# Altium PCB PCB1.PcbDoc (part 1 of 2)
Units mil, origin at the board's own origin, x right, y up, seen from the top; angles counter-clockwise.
Board outline 4950 x 3450 mil, 4 copper layers (Top Layer, VCC, GND, Bottom Layer), stack 79.834 mil thick; 154 components, 59 nets, 358 pads, 74 vias.
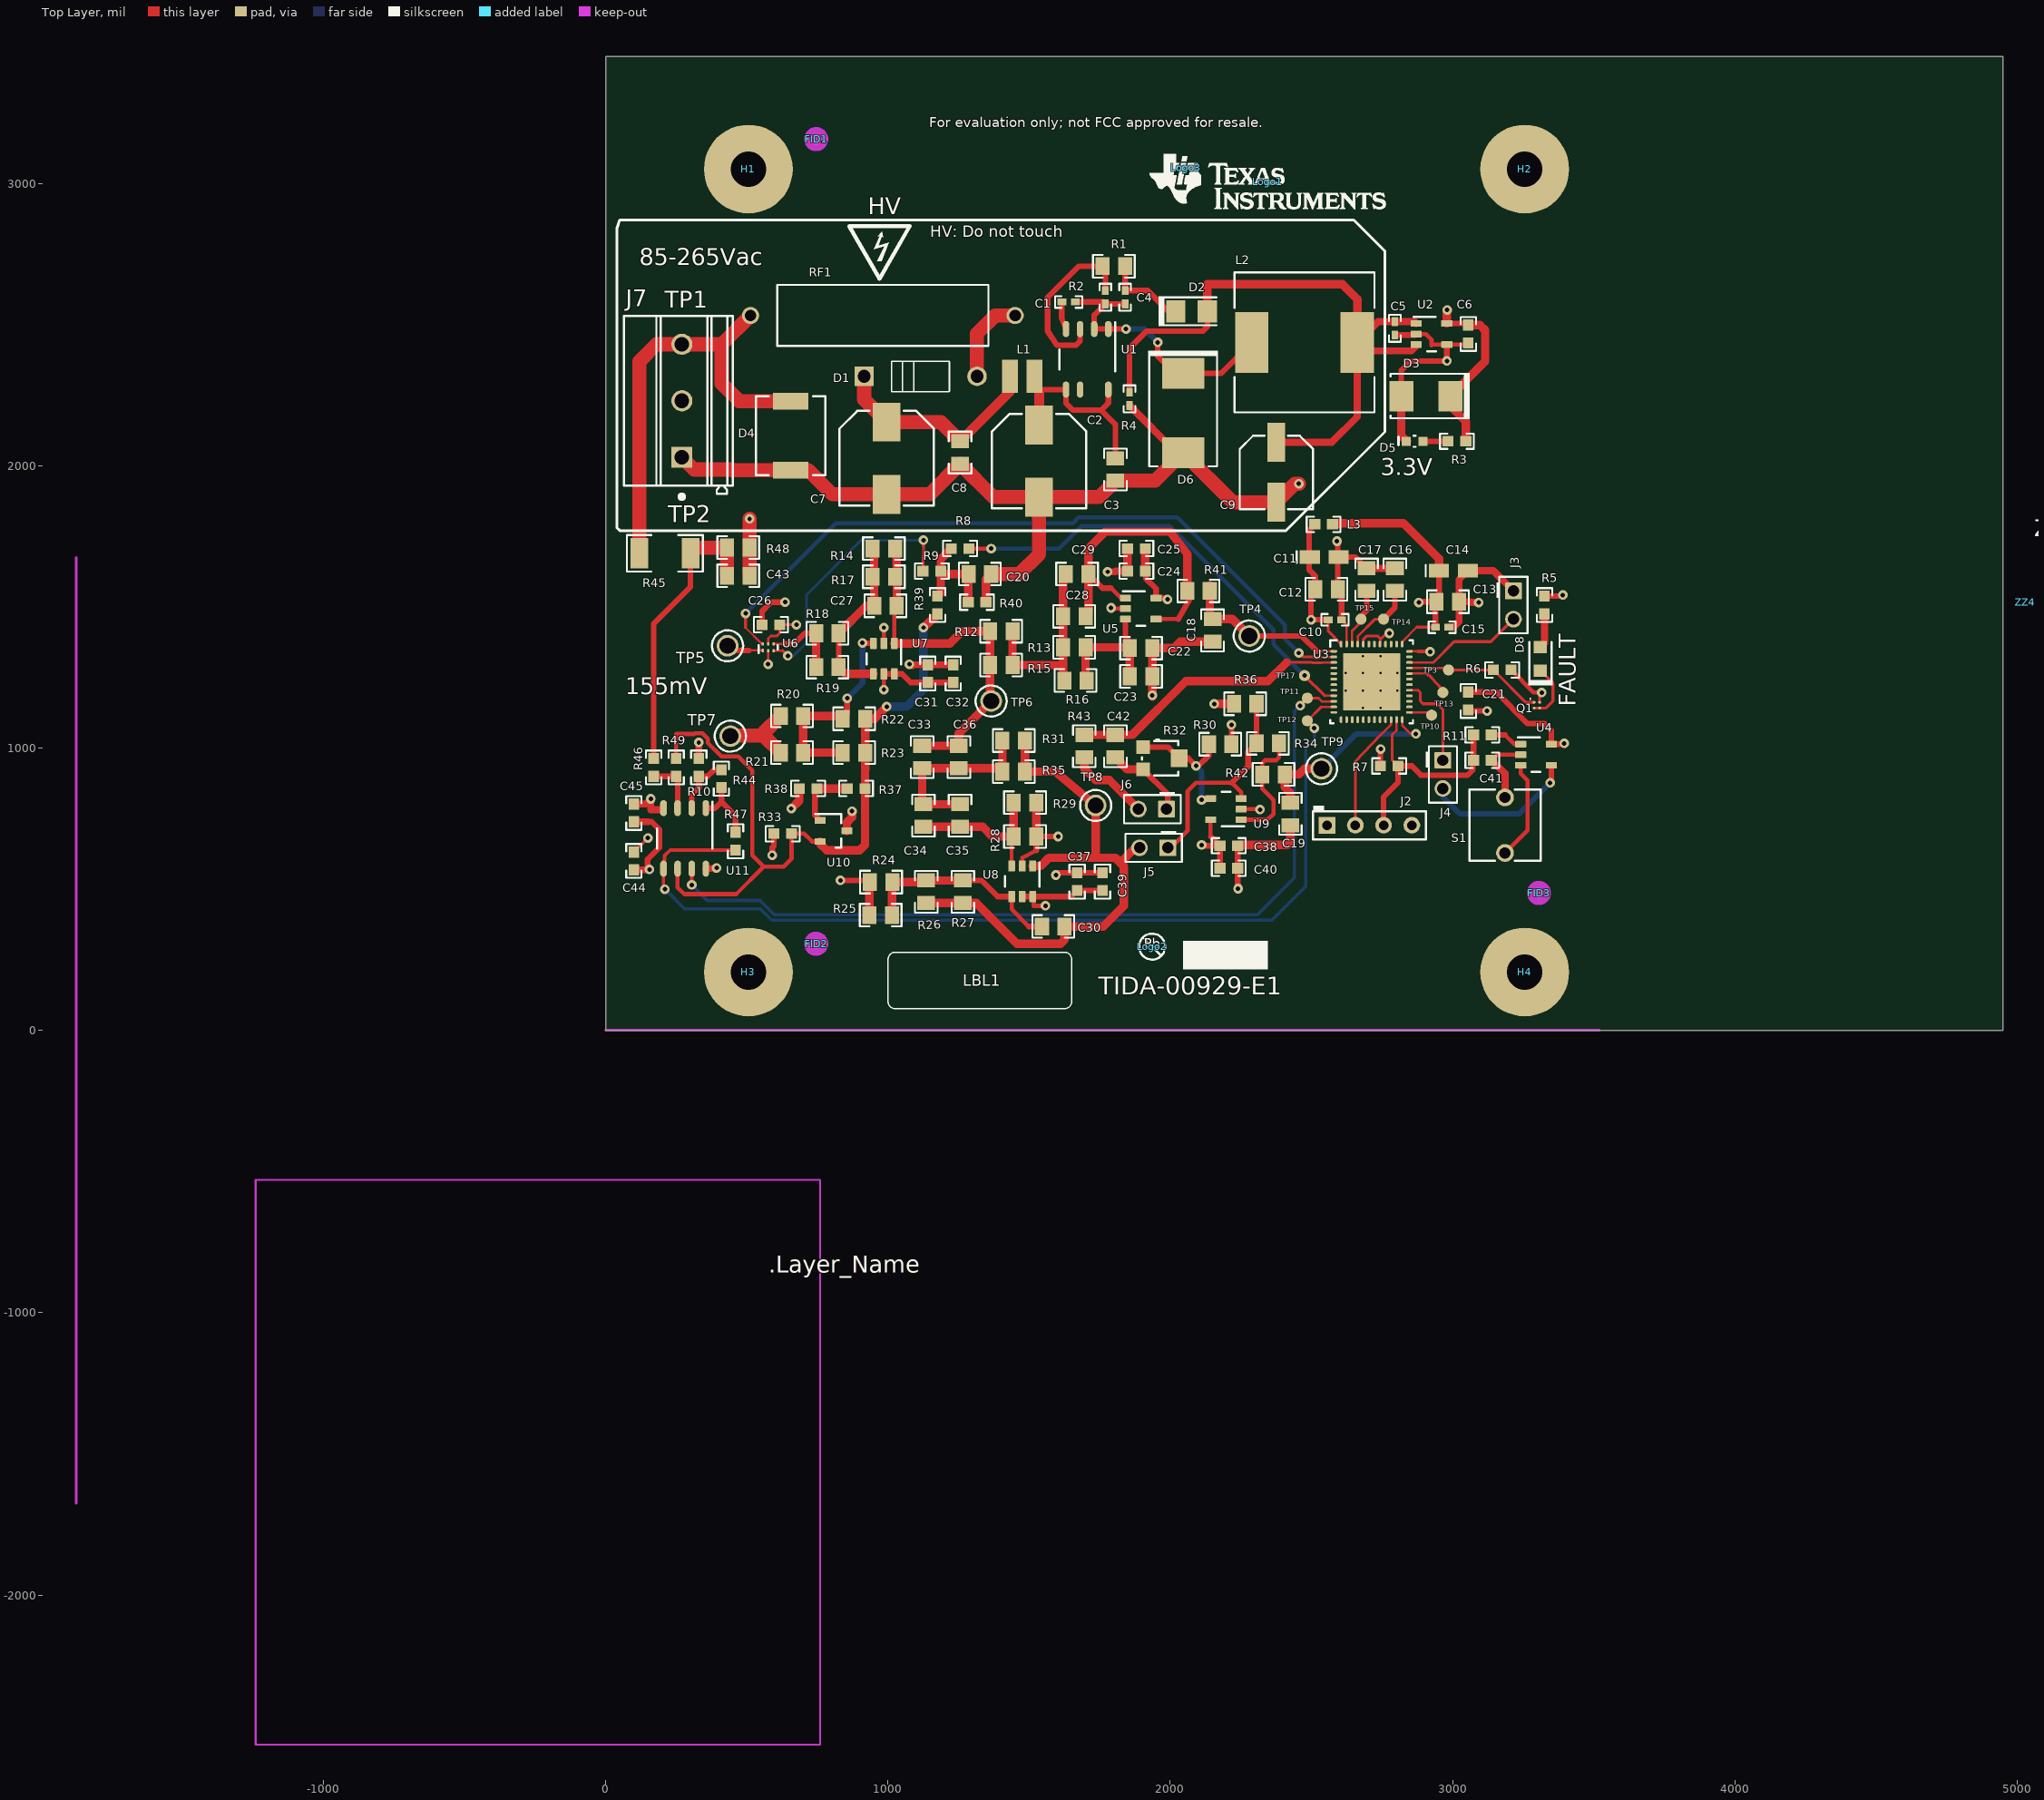
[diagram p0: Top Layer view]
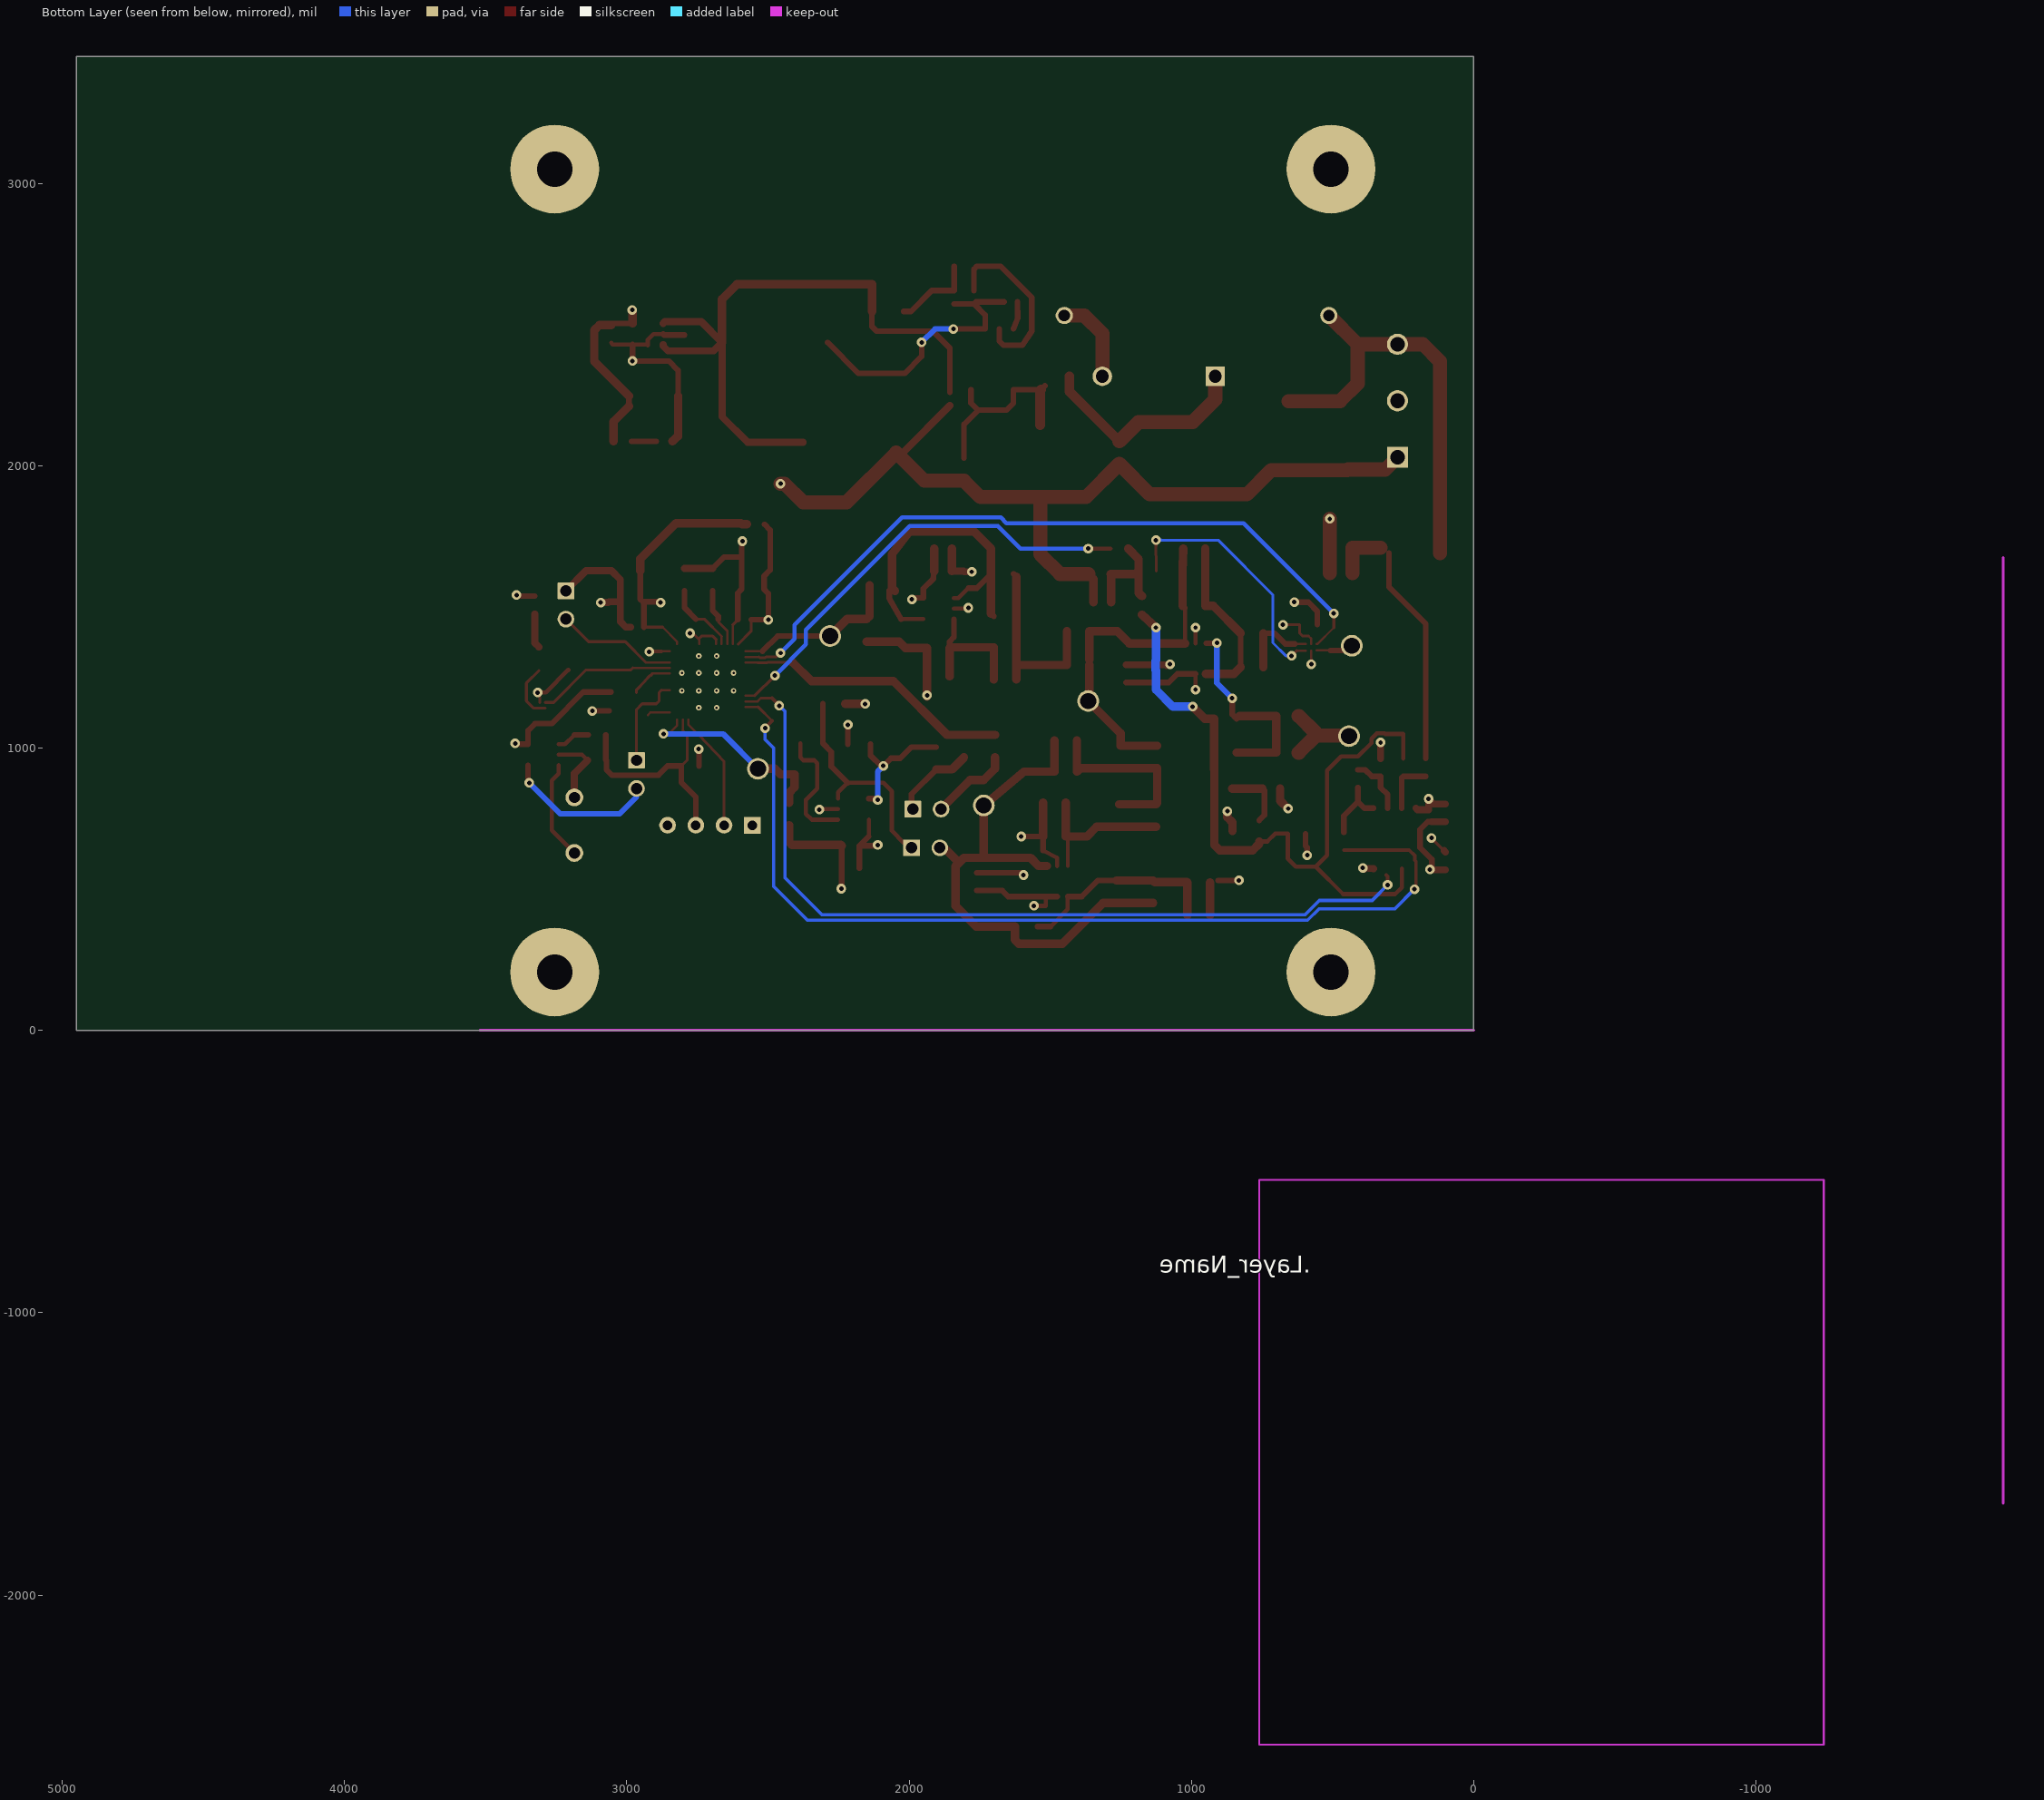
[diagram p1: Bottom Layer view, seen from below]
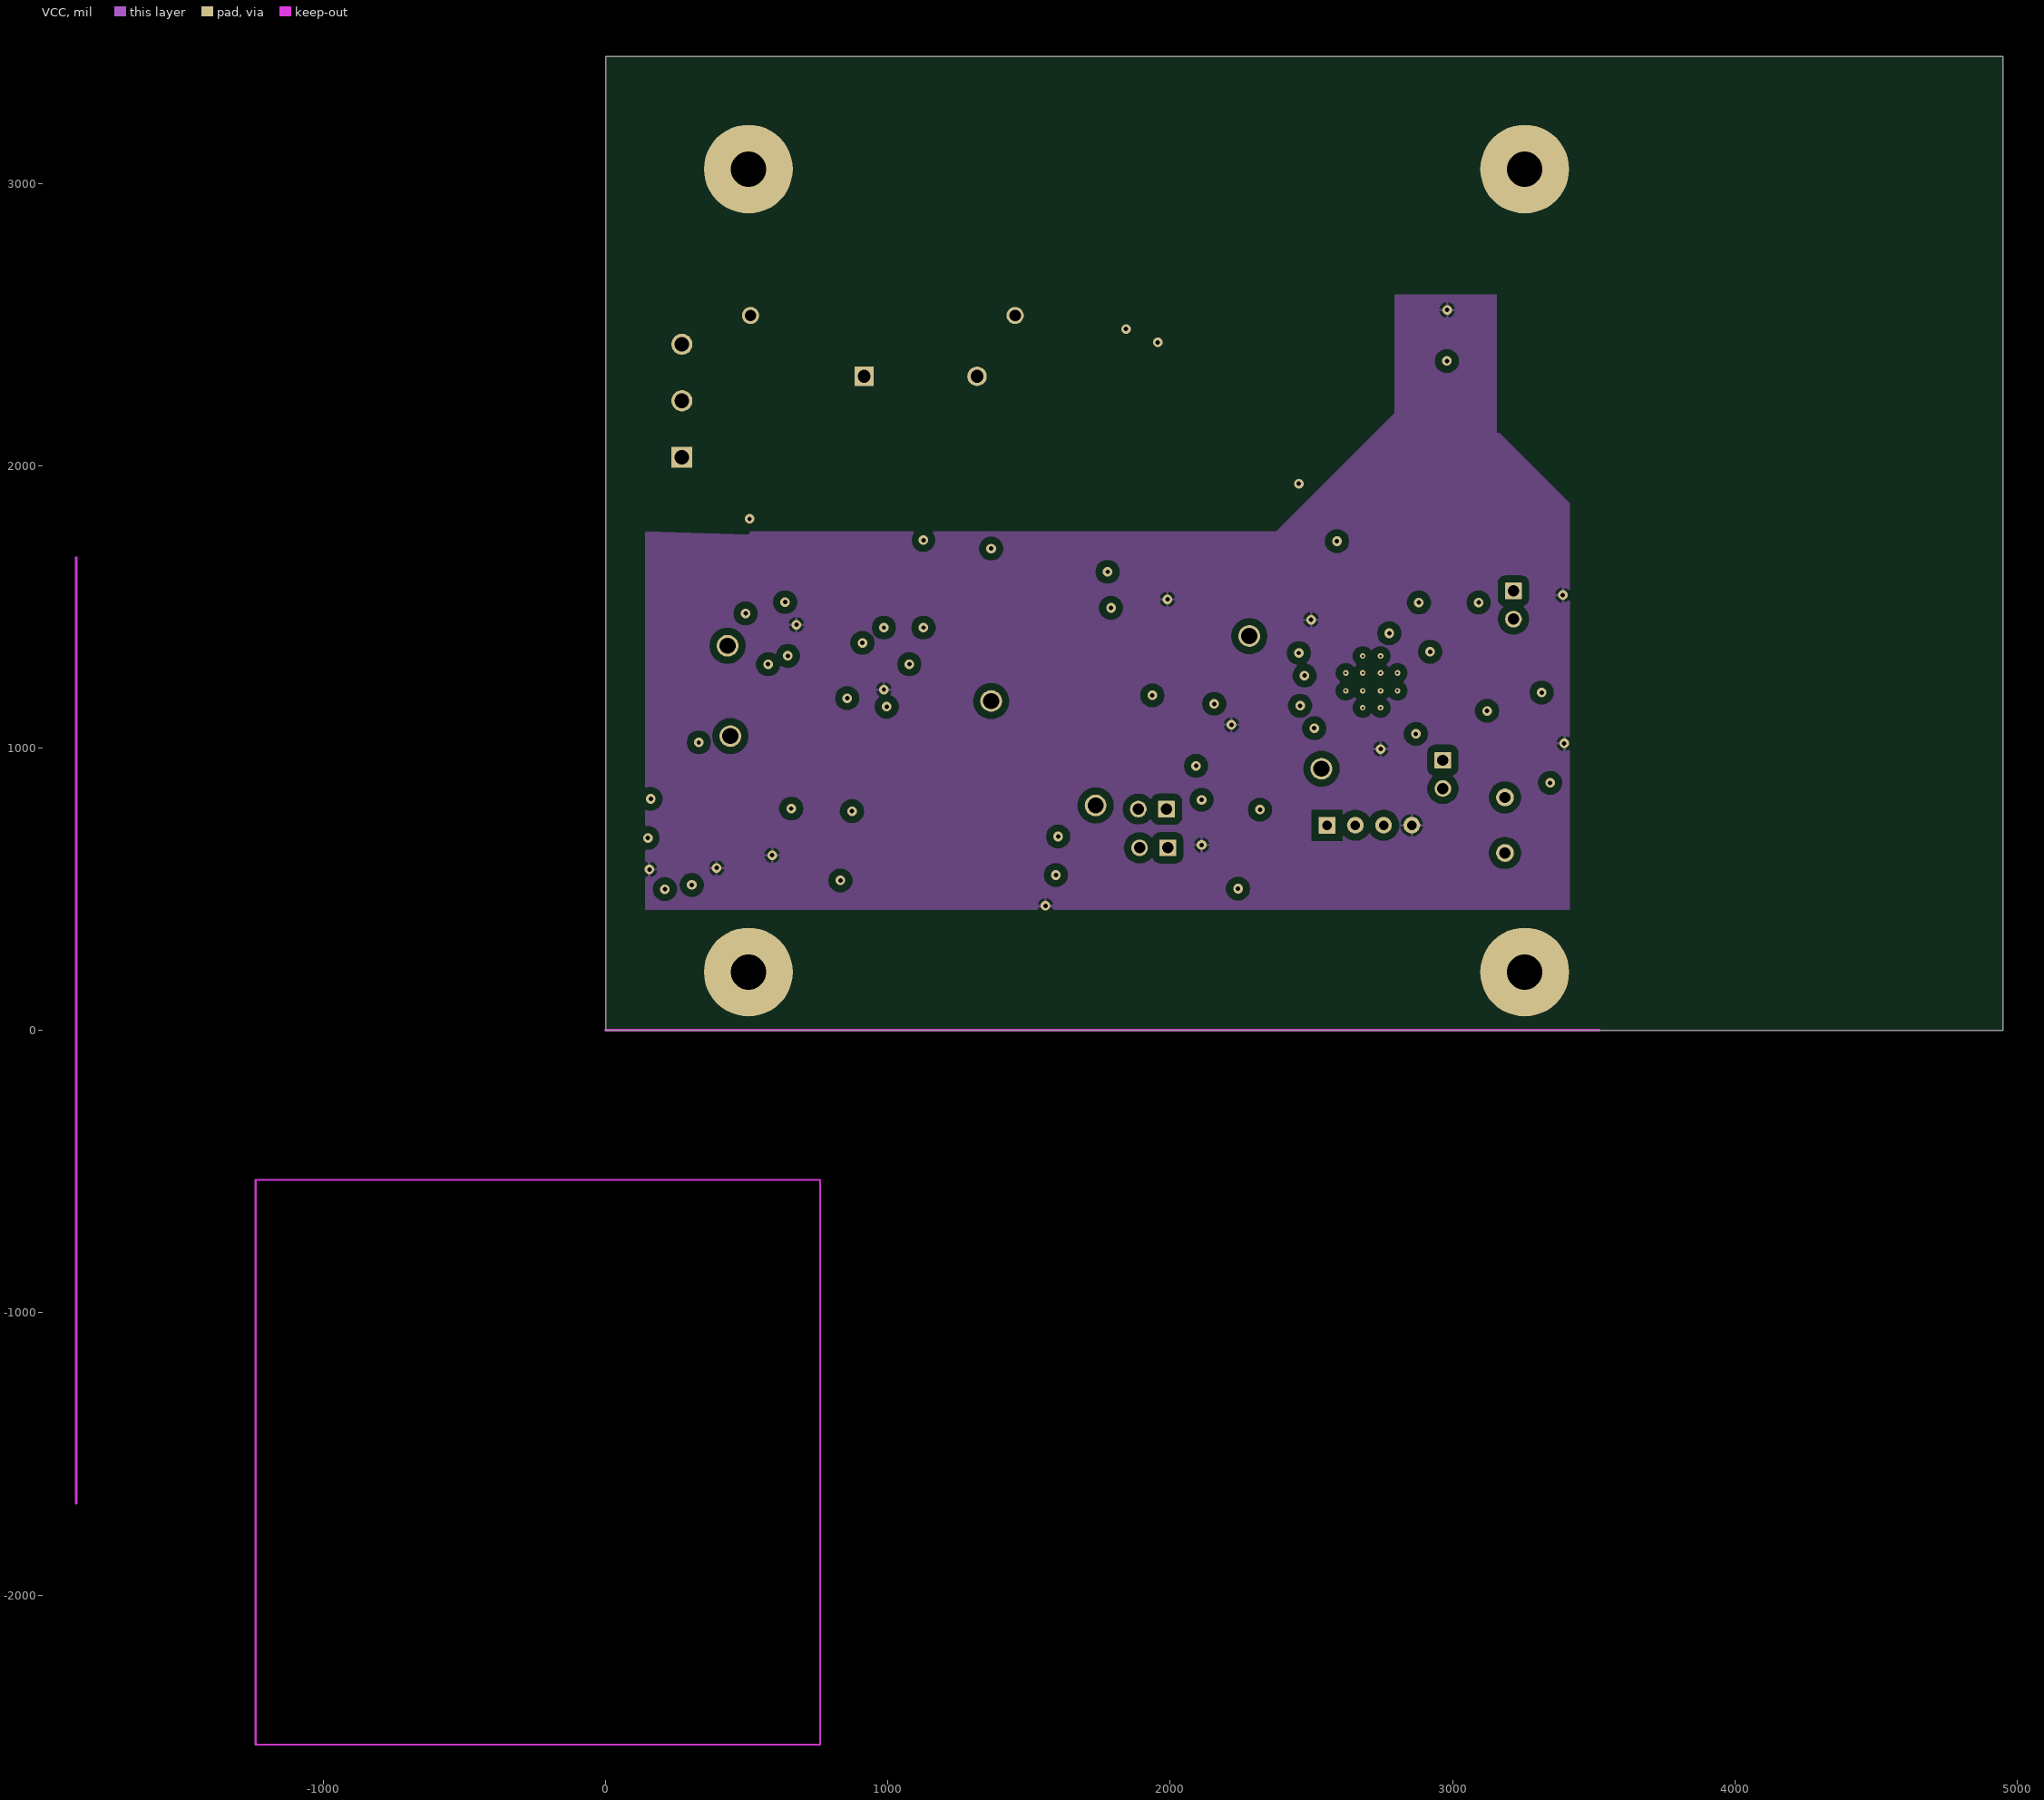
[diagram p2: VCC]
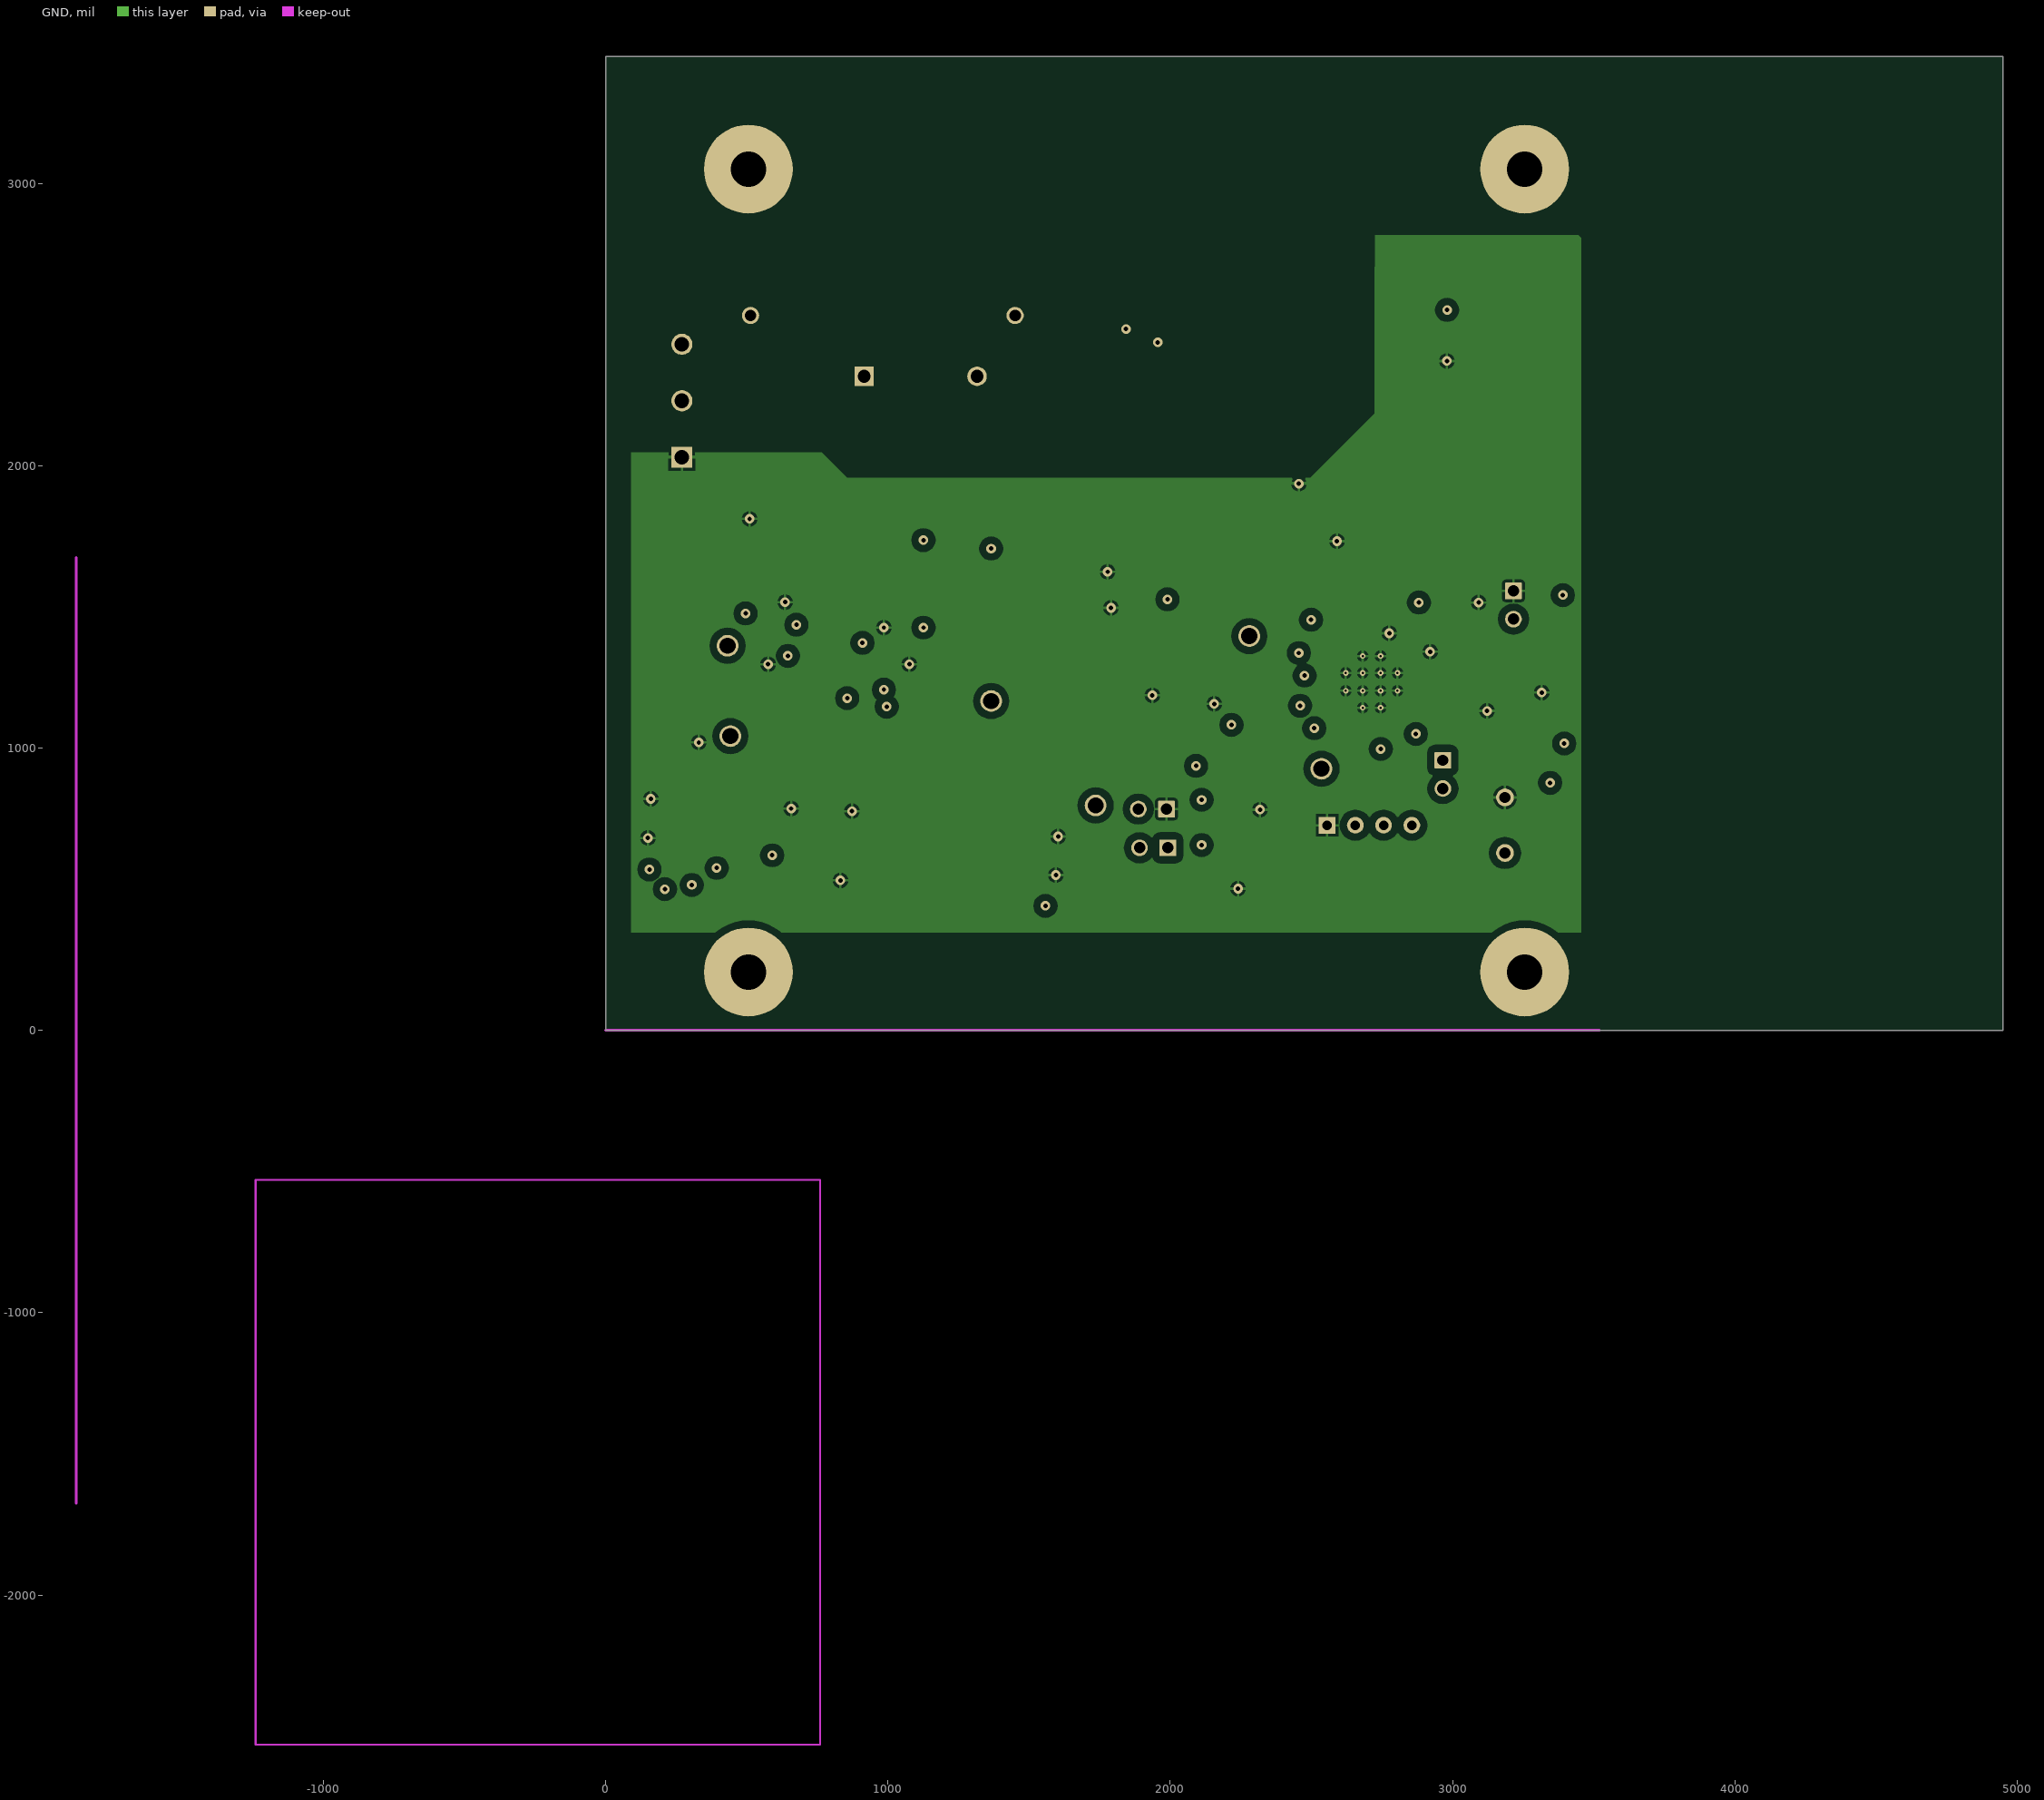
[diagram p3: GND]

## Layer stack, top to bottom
Top Solder: solder mask 0.4, Solder Resist, Dk 3.5
Top Layer: signal copper 1.4
Dielectric1: core 59.2, FR-4, Dk 4.8
VCC: signal copper 1.417
Dielectric 3: prepreg 5, Dk 4.2
GND: signal copper 1.417
Dielectric 2: core 10, Dk 4.2
Bottom Layer: signal copper 1.4
Bottom Solder: solder mask 0.4, Solder Resist, Dk 3.5

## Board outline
0,0 4950,0 4950,3450 0,3450

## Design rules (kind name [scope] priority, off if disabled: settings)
AcuteAngle [All] p1: minimum=4.50000000000000E+0001 checktracksonly=FALSE
AssemblyTestPointUsage [All] p1: valid=2
BoardOutlineClearance BoardOutlineClearance_MountingHoles [OnCopper and InComponentClass('Mounting Holes')] p1: gap=40
BoardOutlineClearance BoardOutlineClearance_Poly [OnCopper and IsPoly] p2: gap=25
BoardOutlineClearance [OnCopper and Not InComponentClass('Logo') and not InComponentClass('FiducialMark') and not InRegion(1000,500,4000,800) and not InPoly] p3: gap=75
Clearance Clearance_Keepouts [((IsTrack Or IsArc) And Not InPoly) And IsFree and IsKeepOut vs ((IsTrack Or IsArc) And Not InPoly) And IsFree and IsKeepOut] p1: gap=0
Clearance Clearance_Poly [InPolygon] p2: gap=25
Clearance [All] p3: gap=7.87
ComponentClearance ComponentClearance_MountingHoles_FiducialMarks [InComponentClass('Mounting Holes') vs InComponentClass('FiducialMark')] p1: gap=50 collisioncheckmode=3 verticalgap=10 showdistances=FALSE
ComponentClearance ComponentClearance_Shunt [InComponentClass('Header') vs InComponentClass('Shunt')] p2: gap=0 collisioncheckmode=3 verticalgap=0 showdistances=FALSE
ComponentClearance ComponentClearance_Logo [InComponentClass('Logo')] p3: gap=50 collisioncheckmode=3 verticalgap=10 showdistances=FALSE
ComponentClearance ComponentClearance_ScrewToNut [(HasFootprint('NY PMS 440 0025 PH')) vs (HasFootprint('Keystone_1902C'))] p4: gap=5 collisioncheckmode=3 verticalgap=10 showdistances=FALSE
ComponentClearance ComponentClearance_MountingHoles [InComponentClass('Mounting Holes')] p5: gap=250 collisioncheckmode=3 verticalgap=100000 showdistances=FALSE
ComponentClearance ComponentClearance_SmallPassives [HasFootprint('0201*') or HasFootprint('0402*') or HasFootprint('0508') or HasFootprint('0603*') or HasFootprint('0612') or HasFootprint('0805*') or HasFootprint('0815*') or HasFootprint('0830*') or HasFootprint('1206*') or HasFootprint('1210*') or HasFootprint('1808*') or HasFootprint('1812*') or HasFootprint('1825*') or HasFootprint('2010*') or HasFootprint('2220*') or HasFootprint('2225*') or HasFootprint('2512*') or HasFootprint('2728*') or HasFootprint('3518*') vs HasFootprint('0201*') or HasFootprint('0402*') or HasFootprint('0508') or HasFootprint('0603*') or HasFootprint('0612') or HasFootprint('0805*') or HasFootprint('0815*') or HasFootprint('0830*') or HasFootprint('1206*') or HasFootprint('1210*') or HasFootprint('1808*') or HasFootprint('1812*') or HasFootprint('1825*') or HasFootprint('2010*') or HasFootprint('2220*') or HasFootprint('2225*') or HasFootprint('2512*') or HasFootprint('2728*') or HasFootprint('3518*')] p6: gap=14.96 collisioncheckmode=3 verticalgap=10 showdistances=FALSE
ComponentClearance ComponentClearance_THtoSMT [IsThruComponent vs IsSMTComponent] p7: gap=40 collisioncheckmode=3 verticalgap=30 showdistances=FALSE
ComponentClearance ComponentClearance_THtoTH [IsThruComponent vs IsThruComponent] p8: gap=30 collisioncheckmode=3 verticalgap=30 showdistances=FALSE
ComponentClearance [All] p9: gap=30 collisioncheckmode=3 verticalgap=10 showdistances=FALSE
DiffPairsRouting [All] p1: maxlimit=100 minlimit=10 mostfreqgap=10 toplayer_minwidth=15 toplayer_maxwidth=15 toplayer_prefwidth=15 midlayer1_minwidth=15 midlayer1_maxwidth=15 midlayer1_prefwidth=15 midlayer2_minwidth=15 midlayer2_maxwidth=15 midlayer2_prefwidth=15 bottomlayer_minwidth=15 bottomlayer_maxwidth=15 bottomlayer_prefwidth=15 maxuncoupledlength=1000
FabricationTestPointUsage TestPointUsage [All] p1: valid=2 allowmultiple=FALSE
FabricationTestpoint Testpoint [All] p1: side=3 testpointundercomponent=TRUE minsize=40 maxsize=100 preferedsize=60 minholesize=0 maxholesize=40 preferedholesize=32 testpointgrid=1 allowsidetop=TRUE allowsidebottom=TRUE usegrid=TRUE gridtolerance=0.01
FanoutControl Fanout_LCC [IsLCC] p1: bgadir=Out bgaviamode=Centered fanoutstyle=Auto fanoutdirection=Alternating viagrid=1 // Fanout_LCC (Default Rule)
FanoutControl Fanout_BGA [IsBGA] p2: bgadir=Out bgaviamode=Centered fanoutstyle=Auto fanoutdirection=Alternating viagrid=1 // Fanout_BGA (Default Rule)
FanoutControl Fanout_Default [All] p4: bgadir=Out bgaviamode=Centered fanoutstyle=Auto fanoutdirection=Alternating viagrid=1 // Fanout_Default (Default Rule)
FanoutControl Fanout_Small [(CompPinCount < 5)] p5: bgadir=Out bgaviamode=Centered fanoutstyle=Auto fanoutdirection=OutThenIn viagrid=1 // Fanout_Small (Default Rule)
HoleSize [All] p1: absolutevalues=TRUE maxlimit=251 minlimit=7.87 maxpercent=80.000 minpercent=20.000
MinimumAnnularRing MinimumAnnularRing_ThermalPadVias [IsVia and InAnyComponent] p1: minimumring=5.91
MinimumAnnularRing [All] p2: minimumring=8
MinimumSolderMaskSliver MinimumSolderMaskSliver_Logo [InComponentClass('Logo') vs InComponentClass('Logo')] p1: minsoldermaskwidth=0.7
MinimumSolderMaskSliver [All] p2: minsoldermaskwidth=3.94
PlaneConnect [All] p1: planeconnectstyle=Relief reliefexpansion=10 reliefentries=4 reliefconductorwidth=10 reliefairgap=10
PolygonConnect [All] p1: connectstyle=Relief reliefconductorwidth=10 reliefentries=4 polygonreliefangle="90 Angle" airgapwidth=10
RoutingVias ThermalPadVias [IsVia and InAnyComponent] p1: holewidth=7.87 width=19.68 viastyle="Through Hole" minholewidth=7.87 minwidth=19.68 maxholewidth=12.99 maxwidth=23.62
RoutingVias [All] p2: holewidth=16 width=34 viastyle="Through Hole" minholewidth=7.87 minwidth=26 maxholewidth=40 maxwidth=65
SilkToBoardRegionClearance [Not ((IsComment or IsDesignator) And (Hide <> 'False')) and not InRegion(1000,500,4000,800)] p1:
SilkToSilkClearance SilkToSilkClearance_Pb-FreeLogo [(HasFootprint('Pb-Free_Overlay_Medium') OR HasFootprint('Pb-Free_Overlay_Small')) vs (HasFootprint('Pb-Free_Overlay_Medium') OR HasFootprint('Pb-Free_Overlay_Small'))] p1: silktosilkclearance=0
SilkToSilkClearance [All] p2: silktosilkclearance=4
SilkToSolderMaskClearance SilkToComponentPadClearance [IsPad and InAnycomponent] p1: minsilkscreentomaskgap=5 clearancetoexposedcopper=TRUE
SilkToSolderMaskClearance "Silk to Solder Mask Opening" [All] p2: minsilkscreentomaskgap=4 clearancetoexposedcopper=FALSE
SolderMaskExpansion [All] p1: expansion=1.97
Width [All] p1: maxlimit=100 minlimit=6 preferedwidth=10 checkconnectedcopper=TRUE
15 further rules are at their usual default settings.

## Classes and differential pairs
component class Label: LBL1
component class AssemblyNote: ZZ1 ZZ2 ZZ3 ZZ4
component class FiducialMark: FID1 FID2 FID3
component class EVM_Hardware: FID1 FID2 FID3 H1 H2 H3 H4 HV LBL1 Logo1 Logo2 Logo3 ZZ1 ZZ2 ZZ3 ZZ4
component class Logo: Logo1
component class "Mounting Holes": H1 H2 H3 H4
component class Header: J2 J3 J4 J5 J6
component class Sheet1: C1 C2 C3 C4 C5 C6 C7 C8 C9 C10 C11 C12 C13 C14 C15 C16 C17 C20 C21 C41 D1 D2 D3 D4 D5 D6 D8 J1 J2 J3 J4 J7 L1 L2 L3 Q1 R1 R2 R3 R4 R5 R6 R7 R8 R9 R11 R39 R40 RF1 S1 TP3 TP10 TP11 TP12 TP13 TP14 TP15 TP17 U1 U2 U3 U4
component class Sheet2: C18 C19 C22 C23 C24 C25 C26 C27 C28 C29 C30 C31 C32 C33 C34 C35 C36 C37 C38 C39 C40 C42 C43 C44 C45 J5 J6 R10 R12 R13 R14 R15 R16 R17 R18 R19 R20 R21 R22 R23 R24 R25 R26 R27 R28 R29 R30 R31 R32 R33 R34 R35 R36 R37 R38 R41 R42 R43 R44 R45 R46 R47 R48 R49 TP4 TP5 TP6 TP7 TP8 TP9 U5 U6 U7 U8 U9 U10 U11

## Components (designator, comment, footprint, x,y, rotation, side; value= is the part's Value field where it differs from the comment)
C1 "C1005X5R1A104K050BA" 0402 1640.04,2580.03 r0 top
C2 "ULR2H2R7MNL1GS" ULR_800X1000 1535.59,2016.56 r270 top
C3 "CC0805JRNP09BN101" 0805_HV 1805.59,1986.56 r270 top
C4 "GRM155R61A683KA01D" 0402 1840.04,2596.56 r270 top
C5 "GRM155R61A105KE15D" 0402 2795.59,2486.56 r270 top
C6 "GRM188R61A335KE15D" 0603 3055.59,2466.56 r270 top
C7 "ULR2H2R7MNL1GS" ULR_800X1000 995.59,2026.56 r270 top
C8 "CC0805JRNP09BN101" 0805_HV 1255.59,2046.56 r270 top
C9 "UUD1A680MCL1GS" SM_RADIAL_6.3AMM 2375.59,1976.56 r270 top
C10 "C1005X5R1A104K050BA" 0402 2583.29,1454.26 r0 top
C11 "TAJA106M010RNJ" 3216-18 2545.59,1676.56 r0 top
C12 "LMK212B7105KD-T" 0805_HV 2553.29,1562.36 r0 top
C13 "LMK212B7105KD-T" 0805_HV 2983.29,1518.02 r0 top
C14 "TAJA106M010RNJ" 3216-18 3003.29,1628.02 r0 top
C15 "C1005X5R1A104K050BA" 0402 2963.29,1428.02 r0 top
C16 "GQM2195C1H220JB01D" 0805_HV 2795.59,1596.56 r270 top
C17 "GQM2195C1H220JB01D" 0805_HV 2695.59,1596.56 r270 top
C18 "GQM2195C2A100JB01D" 0805_HV 2150,1416.56 r270 top
C19 "GQM2195C2A100JB01D" 0805_HV 2425.59,766.56 r270 top
C20 "GQM2195C1H220JB01D" 0805_HV 1325.59,1616.56 r0 top
C21 "06033C104JAT2A" 0603 3055.59,1166.56 r270 top
C22 "CC0805JRNP09BN101" 0805_HV 1896.69,1353.94 r180 top
C23 "CC0805JRNP09BN101" 0805_HV 1896.69,1253.94 r180 top
C24 "C1608X7R1C105K080AC" 0603 1880,1626.56 r180 top
C25 "06033C104JAT2A" 0603 1880,1706.56 r180 top
C26 "06033C104JAT2A" 0603 585.59,1436.56 r0 top
C27 "GQM2195C1H220JB01D" 0805_HV 991.2,1503.63 r0 top
C28 "GRM2165C1H221JA01D" 0805_HV 1660,1466.56 r180 top
C29 "GRM2165C1H221JA01D" 0805_HV 1670,1616.56 r180 top
C30 "GQM2195C1H220JB01D" 0805_HV 1585.59,368.02 r0 top
C31 "C1608X7R1C105K080AC" 0603 1141.2,1263.63 r90 top
C32 "06033C104JAT2A" 0603 1231.2,1263.63 r90 top
C33 "GRM216R71E102KA01D" 0805_HV 1121.2,968.02 r90 top
C34 "GRM216R71E102KA01D" 0805_HV 1125.59,760.95 r90 top
C35 "GRM216R71E102KA01D" 0805_HV 1255.59,760.95 r90 top
C36 "GRM216R71E102KA01D" 0805_HV 1251.2,968.02 r90 top
C37 "C1608X7R1C105K080AC" 0603 1670,526.56 r90 top
C38 "C1608X7R1C105K080AC" 0603 2207.42,653.94 r0 top
C39 "06033C104JAT2A" 0603 1760,526.56 r90 top
C40 "06033C104JAT2A" 0603 2207.42,573.94 r0 top
C41 "06035C132JAT2A" 0603 3105.59,956.56 r0 top
C42 "GQM2195C2A100JB01D" 0805_HV 1805.59,1006.56 r270 top
C43 "GRM216R71E102KA01D" 0805_HV 470,1610 r0 top
C44 "C1608X7R1C105K080AC" 0603 100,600 r90 top
C45 "06033C104JAT2A" 0603 100,770 r90 top
D1 "1N4007" DO-41 1115.59,2316.56 r0 top
D2 "CD1408-FU1800" Diode_1408 2075.59,2546.56 r0 top
D3 "1SMB5914BT3G" SMB 2905.28,2246.56 r180 top
D4 "SMCJ400CA" DO-214AB-Bi 655.59,2106.56 r90 top
D5 "LG L29K-G2J1-24-Z" "LG L29K_GREEN" 2865.28,2086.56 r180 top
D6 "ES3J" SMC 2045.59,2186.56 r270 top
D8 "150080SS75000" WL-SMCW_RED_0805 3310.99,1315.92 r90 top
FID1 "Fiducial" Fiducial10-20 745.59,3156.56 r0 top
FID2 "Fiducial" Fiducial10-20 745.59,306.56 r0 top
FID3 "Fiducial" Fiducial10-20 3305.59,486.56 r0 top
H1 "NY PMS 440 0025 PH" "NY PMS 440 0025 PH" 505.59,3050.56 r0 top locked
H2 "NY PMS 440 0025 PH" "NY PMS 440 0025 PH" 3255.59,3050.56 r0 top locked
H3 "NY PMS 440 0025 PH" "NY PMS 440 0025 PH" 505.59,206.56 r0 top locked
H4 "NY PMS 440 0025 PH" "NY PMS 440 0025 PH" 3255.59,206.56 r0 top locked
HV "DANGER HIGH VOLTAGE" IEC_HighVoltage_Small 970,2760 r180 top
J2 "800-10-004-10-001000" Mill-Max_800-10-004-10-001000 2705.59,726.56 r0 top
J3 "PEC02SAAN" CONN_PEC02SAAN 3215.59,1506.56 r270 top
J4 "PEC02SAAN" CONN_PEC02SAAN 2965.59,906.56 r270 top
J5 "PEC02SAAN" CONN_PEC02SAAN 1941.18,646.56 r180 top
J6 "PEC02SAAN" CONN_PEC02SAAN 1936.79,783.63 r180 top
J7 "1715734" Phoenix_1715734 270,2230 r90 top
L1 "SDR0302-471KL" SDR0302 1475.59,2316.56 r0 top
L2 "MSS1210-125KE" MSS1210 2475.59,2436.56 r0 top
L3 "BLM18SG331TN1D" 0603 2543.29,1792.36 r180 top
LBL1 "Size: 0.65\" x 0.20 \"" Label_650x200 1325.59,176.56 r0 top
Logo1 "Texas Instruments" TI_Stacked_Overlay_Small 2345.59,3006.56 r0 top
Logo2 "Pb-Free Symbol" Pb-Free_Overlay_Small 1935.59,296.56 r0 top
Logo3 "FCC disclaimer" FCC_disclaimer 2055.59,3056.56 r0 top
Q1 "CSD13201W10" uSMD_4A 3298.69,1151.72 r0 top
R1 "RT0805BRD0739K7L" 0805_HV 1800.04,2706.56 r0 top
R2 "CRCW040210K2FKED" 0402 1770.04,2596.56 r90 top
R3 "CRCW0603300RJNEA" 0603 3015.28,2086.56 r0 top
R4 "CRCW04024K99FKED" 0402 1855.59,2236.56 r90 top
R5 "CRCW0603300RJNEA" 0603 3325.59,1506.56 r270 top
R6 "CRCW0603100KFKEA" 0603 3175.59,1276.56 r180 top
R7 "CRCW060347K0JNEA" 0603 2775.59,936.56 r180 top
R8 "CRCW06030000Z0EA" 0603 1255.59,1706.56 r180 top
R9 "CRCW06030000Z0EA" 0603 1155.59,1626.56 r180 top
R10 "CRCW060347K0JNEA" 0603 330,931.3 r270 top
R11 "CRCW06030000Z0EA" 0603 3105.59,1046.56 r180 top
R12 "CRCW080551K0JNEA" 0805_HV 1401.2,1413.63 r0 top
R13 "CRCW080551K0JNEA" 0805_HV 1660,1356.56 r0 top
R14 "CRCW0805100KFKEA" 0805_HV 985.59,1706.56 r0 top
R15 "CRCW080551K0JNEA" 0805_HV 1401.2,1293.94 r0 top
R16 "CRCW080551K0JNEA" 0805_HV 1664.39,1239.18 r0 top
R17 "CRCW0805100KFKEA" 0805_HV 985.59,1606.56 r0 top
R18 "CRCW080510K0FKEA" 0805_HV 785.59,1406.56 r0 top
R19 "CRCW080510K0FKEA" 0805_HV 785.59,1286.56 r0 top
R20 "CRCW080510K0FKEA" 0805_HV 660,1113.63 r0 top
R21 "CRCW080510K0FKEA" 0805_HV 660,983.63 r0 top
R22 "CRCW0805100KFKEA" 0805_HV 880,1103.63 r0 top
R23 "CRCW0805100KFKEA" 0805_HV 880,983.63 r0 top
R24 "CRCW080520K0FKEA" 0805_HV 975.59,525.1 r180 top
R25 "CRCW080520K0FKEA" 0805_HV 974.39,408.04 r180 top
R26 "CRCW0805180KJNEA" 0805_HV 1135.59,490.99 r270 top
R27 "CRCW0805180KJNEA" 0805_HV 1265.59,490.99 r270 top
R28 "CRCW080520K0FKEA" 0805_HV 1485.59,686.56 r180 top
R29 "CRCW080520K0FKEA" 0805_HV 1485.59,806.56 r180 top
R30 "CRCW0805100KFKEA" 0805_HV 2176.79,1013.63 r0 top
R31 "CRCW0805120KJNEA" 0805_HV 1445.59,1026.56 r0 top
R32 "EVM-3YSX50B25" Panasonic_EVM-3Y 1966.79,963.63 r270 top
R33 "CRCW06033K40FKEA" 0603 627.24,696.56 r0 top
R34 "CRCW08053M83FKEA" 0805_HV 2345.59,1016.56 r0 top
R35 "CRCW0805120KJNEA" 0805_HV 1445.59,916.56 r0 top
R36 "CRCW0805200KJNEA" 0805_HV 2265.59,1156.56 r0 top
R37 "CRCW060329K4FKEA" 0603 887.24,856.56 r0 top
R38 "CRCW0603100KFKEA" 0603 717.24,856.56 r0 top
R39 "CRCW06030000Z0EA" 0603 1175.59,1506.56 r90 top
R40 "CRCW06030000Z0EA" 0603 1315.59,1516.56 r180 top
R41 "CRCW0805402KFKEA" 0805_HV 2099.98,1556.56 r0 top
R42 "CRCW08050000Z0EA" 0805_HV 2365.59,906.56 r0 top
R43 "CRCW08051K00JNEA" 0805_HV 1695.59,1006.56 r270 top
R44 "CRCW060347K0JNEA" 0603 410,891.3 r270 top
R45 "CRCW2010300KFKEF" 2010 210,1690 r180 top
R46 "CRCW060347K0JNEA" 0603 170,931.3 r270 top
R47 "CRCW060310R0FKEA" 0603 460,670 r270 top
R48 "CRCW08051K10FKEA" 0805_HV 470,1710 r180 top
R49 "CRCW060347K0JNEA" 0603 250,931.3 r270 top
RF1 "AC03000001009JACCS" AC03 981.86,2532.18 r180 top
S1 "EVQ-21505R" SW_EVQ-21x05 3185.59,726.56 r270 top
TP3 "TESTPOINT" TP_SM_1MM 2985.59,1276.56 r90 top
TP4 "Suggest using a net name here" Mill-Max_0253-0-15-15-30-27-10-0 2280,1396.56 r0 top
TP5 "Suggest using a net name here" Mill-Max_0253-0-15-15-30-27-10-0 431.86,1362.18 r0 top
TP6 "Suggest using a net name here" Mill-Max_0253-0-15-15-30-27-10-0 1365.59,1166.56 r0 top
TP7 "Suggest using a net name here" Mill-Max_0253-0-15-15-30-27-10-0 441.86,1042.18 r0 top
TP8 "Suggest using a net name here" Mill-Max_0253-0-15-15-30-27-10-0 1735.59,796.56 r0 top
TP9 "Suggest using a net name here" Mill-Max_0253-0-15-15-30-27-10-0 2535.59,926.56 r0 top
TP10 "TESTPOINT" TP_SM_1MM 2925.59,1116.56 r90 top
TP11 "TESTPOINT" TP_SM_1MM 2485.59,1176.56 r90 top
TP12 "TESTPOINT" TP_SM_1MM 2485.59,1096.56 r90 top
TP13 "TESTPOINT" TP_SM_1MM 2965.59,1196.56 r90 top
TP14 "TESTPOINT" TP_SM_1MM 2755.59,1456.56 r90 top
TP15 "TESTPOINT" TP_SM_1MM 2675.59,1456.56 r90 top
TP17 "TESTPOINT" TP_SM_1MM 2475.59,1256.56 r90 top
U1 "UCC28880DR" D0007A_N 1705.59,2376.88 r270 top
U2 "LP5907MFX-3.3/NOPB" DBV0005A_N 2925.59,2466.56 r0 top
U3 "MSP430FR5994IRGZR" RGZ0048A 2713.29,1234.26 r0 top
U4 "TPS3828-33QDBVRQ1" DBV0005A_N 3295.59,976.25 r0 top
U5 "TLV316IDBVR" DBV0005A_N 1895.59,1493.94 r0 top
U6 "SN74LVC1G3157DRYR" DRY0006A 575.59,1356.56 r90 top
U7 "OPA835IDBVR" DBV0006A_N 985.59,1316.56 r270 top
U8 "OPA836IDBVR" DBV0006A_N 1475.59,528.02 r270 top
U9 "TLV3201AIDBVR" DBV0005A_N 2197.11,783.63 r180 top
U10 "TLV431AIDBZR" DBZ0003A_N 807.24,706.56 r0 top
U11 "LMV612MA" D0008A_N 280,680 r270 top
ZZ1 "This Assembly Note is for PCB labels only" AssemblyNoteLabel 5748,246 r90 top
ZZ2 "These assemblies are ESD sensitive, ESD precautions shall be observed." AssemblyNote 5508,2746 r90 top
ZZ3 "These assemblies must be clean and free from flux and all contaminants. Use of no clean flux is not acceptable." AssemblyNote 5268,1196 r90 top
ZZ4 "These assemblies must comply with workmanship standards IPC-A-610 Class 2, unless otherwise specified." AssemblyNote 5028,1516 r90 top

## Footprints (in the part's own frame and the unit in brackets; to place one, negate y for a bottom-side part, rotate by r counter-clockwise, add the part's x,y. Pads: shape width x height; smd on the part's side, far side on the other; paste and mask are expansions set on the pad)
0402 [mm] "0402 from SM-752 data"
  rect 0.8x0.6 smd: 1(-0.6,0) 2(0.6,0)
  silkscreen extent -1.22,-0.52 1.22,0.52, body extent -0.55,-0.3 0.55,0.3, height 0.6
0603 [mm] "0603 from SM-752 data"
  rect 1x0.95 smd: 1(-0.8,0) 2(0.8,0)
  silkscreen extent -1.52,-0.69 1.52,0.69, body extent -0.87,-0.47 0.87,0.47, height 1
0805_HV [mil] "0805 with 30mil clearance between pads"
  rect 50x63 smd: 1(-40,0) 2(40,0)
  silkscreen extent -74,-40 74,40, body extent -43,-29 43,29, height 57
2010 [mm] "Chip Capacitor, Body 5.08x2.54mm, IPC Medium Density"
  rect 1.6x2.7 smd: 1(-2.3,0) 2(2.3,0)
  silkscreen extent -3.42,-1.65 3.42,1.65, body extent -2.73,-1.45 2.73,1.45, height 1.66
3216-18 [mm] "Medium density IPC, based on Kemet T495 dimensions"
  rect 1.8x1.25 smd: 1(-1.3,0) 2(1.3,0)
  silkscreen extent -2.49,-0.54 -2.49,0.54, body extent -1.7,-0.9 1.7,0.9, height 1.8
AC03 [mm] "TH, 2-Leads, Axial, Dia 5.5mm, Pin Spacing 23.8mm"
  round 1.55 hole 1.05: 1(-11.9,0) 2(11.9,0)
  silkscreen extent -9.5,-2.75 9.5,2.75, body extent -12.3,-2.74 12.3,2.74, height 5.48
AssemblyNote [mil] "Assembly Note"
AssemblyNoteLabel [mil] "Assembly Note for PCB Labels"
CONN_PEC02SAAN [mm] "SULLINS"
  rrect7% 1.5x1.5 hole 1.016: 1(-1.27,0)
  round 1.5 hole 1.016: 2(1.27,0)
  silkscreen extent -2.54,-1.52 2.54,1.27, body extent -2.54,-1.27 2.54,1.27, height 8.38
D0007A_N [mm] "SOIC, 7-Leads, Body 4.9x3.9mm, Pitch 1.27mm, IPC Medium Density"
  oval 1.45x0.6 smd: 1(-2.725,1.905) 2(-2.725,0.635) 3(-2.725,-0.635) 4(-2.725,-1.905) 5(2.725,-1.905) 6(2.725,-0.635) 8(2.725,1.905)
  silkscreen extent -3.32,-2.5 1.1,2.52, body extent -3.01,-2.45 3.01,2.45, height 1.75
D0008A_N [mm] "SOIC, 8-Leads, Body 4.9x3.9mm, Pitch 1.27mm, IPC Medium Density"
  oval 1.45x0.6 smd: 1(-2.725,1.905) 2(-2.725,0.635) 3(-2.725,-0.635) 4(-2.725,-1.905) 5(2.725,-1.905) 6(2.725,-0.635) 7(2.725,0.635) 8(2.725,1.905)
  silkscreen extent -3.3,-2.5 0.9,2.5, body extent -3,-2.45 3,2.45, height 1.63
DBV0005A_N [mm] "SOT23, 5-Leads, Body 2.9x1.6mm, Pitch 0.95mm, Lead Span 2.8mm, IPC Medium Density"
  rrect17% 1x0.6 smd: 1(-1.375,0.95) 2(-1.375,0) 3(-1.375,-0.95) 4(1.375,-0.95) 5(1.375,0.95)
  silkscreen extent -1.63,-1.55 0.38,1.55, body extent -1.42,-1.46 1.42,1.46, height 1.09
DBV0006A_N [mm] "SOT23, 6-Leads, Body 2.9x1.6mm, Pitch 0.95mm, Lead Span 2.8mm, IPC Medium Density"
  rrect17% 1x0.6 smd: 1(-1.375,0.95) 2(-1.375,0) 3(-1.375,-0.95) 4(1.375,-0.95) 5(1.375,0) 6(1.375,0.95)
  silkscreen extent -1.68,-1.55 0.5,1.55, body extent -1.42,-1.46 1.42,1.46, height 1.12
DBZ0003A_N [mm] "SOT23, 3-Leads, Body 2.9x1.3mm, Pitch 0.95mm, Lead Span 2.4mm, IPC Medium Density"
  rrect17% 1x0.6 smd: 1(-1.2,0.95) 2(-1.2,-0.95) 3(1.2,0)
  silkscreen extent -1.65,-1.5 0.7,1.5, body extent -1.26,-1.46 1.26,1.46, height 0.98
Diode_1408 [mm] "On Semi recommended land pattern for SOD-123"
  rect 1.75x2 smd: 1(-1.425,0) 2(1.425,0)
  silkscreen extent -2.97,-1.35 2.26,1.35, body extent -1.8,-1.05 1.8,1.05, height 1.35
DO-41 [mm] "diode"
  rect 1.75x1.75 hole 1.15: 1(-5.08,0)
  round 1.75 hole 1.15: 2(5.08,0)
  silkscreen extent -2.62,-1.37 2.59,1.35, body extent -5.51,-1.36 5.51,1.36, height 2.72
DO-214AB-Bi [mm] "Vishay recommended land pattern 20-Dec-13"
  rect 1.52x3.2 smd: 1(-3.105,0) 2(3.105,0)
  silkscreen extent -3.55,-3.11 3.55,3.11, body extent -3.55,-3.11 3.55,3.11, height 2.62
DRY0006A [mm] "PSON, 6-Leads, Body 1x1.45mm, Pitch 0.5mm, TI Recommended"
  rect 0.35x0.2 smd: 1(-0.275,0.5)
  rect 0.3x0.2 smd: 2(-0.3,0) 3(-0.3,-0.5) 4(0.3,-0.5) 5(0.3,0) 6(0.3,0.5)
  silkscreen extent -0.5,-0.85 0.2,0.85, body extent -0.53,-0.75 0.53,0.75, height 0.61
FCC_disclaimer [mil]
Fiducial10-20 [mm]
  round 1 smd mask+0.5: 1(0,0)
  Top Layer keep-out circle w1.178: c0,0 r0.5
IEC_HighVoltage_Small [mil]
  silkscreen extent -107,-88 107,97
Label_650x200 [mil] "Thermal Transfer Label"
  silkscreen extent -325,-100 325,100, body extent -325,-100 325,100, height 1
"LG L29K_GREEN" [mm] "OSRAM"
  rect 0.8x0.8 smd paste-0.4: 1(-0.75,0) 2(0.75,0)
  silkscreen extent -0.1,-0.5 1.45,0.5, body extent -0.9,-0.45 0.9,0.45, height 0.67
Mill-Max_0253-0-15-15-30-27-10-0 [mm] "Pin Receptacle, Dia 0.015-0.025\", Length 0.173\", TH"
  round 1.95 hole 1.448: 1(0,0)
  silkscreen extent -1.4,-1.4 1.4,1.4, body extent -0.91,-0.91 0.91,0.91, height 0.79
Mill-Max_800-10-004-10-001000 [mm] "Mill-Max"
  rect 1.5x1.5 hole 0.85: 1(-3.81,0)
  round 1.5 hole 0.85: 2(-1.27,0) 3(1.27,0) 4(3.81,0)
  silkscreen extent -5.08,-1.27 5.08,1.78, body extent -5.08,-1.27 5.08,1.27, height 8.13
MSS1210 [mm] "Coilcraft MSS1210 series"
  rect 3x5.5 smd: 1(-4.75,0) 2(4.75,0)
  silkscreen extent -6.3,-6.3 6.3,6.3, body extent -6.15,-6.15 6.15,6.15, height 10.2
"NY PMS 440 0025 PH" [mm] "4-40 nylon screw and mounting hole"
  round 8 hole 3.2: 1(0,0)
  body extent -3.3,-3.3 3.3,3.3, height 2.69
Panasonic_EVM-3Y [mm] "SMD, 3-Leads, Body 3.1x3.45mm"
  rect 1.2x1.2 smd: 1(-1,-1.6) 3(1,-1.6)
  rect 1.6x1.5 smd: 2(0,1.65)
  silkscreen extent -1.8,-1.7 1.55,1.55, body extent -1.55,-1.9 1.55,1.55, height 1.55
Pb-Free_Overlay_Small [mil]
  silkscreen extent -46,-46 46,46
Phoenix_1715734 [mm] "Phoenix"
  rect 1.9x1.9 hole 1.321: 1(-5.08,0)
  round 1.9 hole 1.321: 2(0,0) 3(5.08,0)
  silkscreen extent -8.76,-4.6 7.62,5.2, body extent -8.36,-4.6 7.62,5.2, height 14.2
RGZ0048A [mm] "QFN, 48-Leads, Body 7x7mm, Pitch 0.5mm, Thermal Pad 5.15X5.15mm, TI recommended"
  oval 0.6x0.24 smd: 1(-3.4,2.75) 2(-3.4,2.25) 3(-3.4,1.75) 4(-3.4,1.25) 5(-3.4,0.75) 6(-3.4,0.25) 7(-3.4,-0.25) 8(-3.4,-0.75) 9(-3.4,-1.25) 10(-3.4,-1.75) 11(-3.4,-2.25) 12(-3.4,-2.75) 25(3.4,-2.75) 26(3.4,-2.25) 27(3.4,-1.75) 28(3.4,-1.25) 29(3.4,-0.75) 30(3.4,-0.25) 31(3.4,0.25) 32(3.4,0.75) 33(3.4,1.25) 34(3.4,1.75) 35(3.4,2.25) 36(3.4,2.75)
  oval 0.24x0.6 smd: 13(-2.75,-3.4) 14(-2.25,-3.4) 15(-1.75,-3.4) 16(-1.25,-3.4) 17(-0.75,-3.4) 18(-0.25,-3.4) 19(0.25,-3.4) 20(0.75,-3.4) 21(1.25,-3.4) 22(1.75,-3.4) 23(2.25,-3.4) 24(2.75,-3.4) 37(2.75,3.4) 38(2.25,3.4) 39(1.75,3.4) 40(1.25,3.4) 41(0.75,3.4) 42(0.25,3.4) 43(-0.25,3.4) 44(-0.75,3.4) 45(-1.25,3.4) 46(-1.75,3.4) 47(-2.25,3.4) 48(-2.75,3.4)
  rect 5.15x5.15 smd paste-2.6: 49(0,0)
  silkscreen extent -3.72,-3.72 3.72,3.72, body extent -3.58,-3.57 3.57,3.58, height 1.01
SDR0302 [mm] "BOURNS"
  rect 1.4x3 smd: 1(-1.1,0) 2(1.1,0)
  body extent -1.65,-1.65 1.65,1.65, height 2.8
SM_RADIAL_6.3AMM [mm] "Nichicon 6.3x5.8"
  rect 3.5x1.6 smd: 1(-2.7,0) 2(2.7,0)
  silkscreen extent -3.3,-3.29 3.3,3.31, body extent -3.5,-3.3 3.5,3.3, height 6.11
SMB [mil] "Molded Diode, 2-Leads, Body 5.4x3.6mm, IPC Medium Density, based on OnSemi component dimensions"
  rect 85x107.99 smd: 1(-87.01,0) 2(87.01,0)
  silkscreen extent -155,-82 125,82, body extent -106,-71 106,71, height 91
SMC [mil] "Molded Diode, 2-Leads, Body 6.9x5.8mm, IPC Medium Density, based on OnSemi component dimensions and land patterns"
  rect 110x150 smd: 1(-140.49,0) 2(140.49,0)
  silkscreen extent -221,-124 189,123, body extent -156,-116 156,116, height 91
SW_EVQ-21x05 [mm] "Panasonic"
  round 1.6 hole 1: 1(-2.5,0) 2(2.5,0)
  silkscreen extent -3.2,-3.2 3.2,3.2, body extent -3.15,-3.15 3.15,3.15, height 5.2
TI_Stacked_Overlay_Small [mil]
  silkscreen extent -418,-98 418,98
TP_SM_1MM [mm] "1mm Test Point, SMT"
  round 1 smd paste-0.5: 1(0,0)
ULR_800X1000 [mm] "SMD, 2-Leads, Dia 8mm"
  rect 3.5x2.5 smd: 1(-3.25,0) 2(3.25,0)
  silkscreen extent -4.25,-4.25 4.25,4.25, body extent -4.25,-4.25 4.25,4.25, height 11
uSMD_4A [mm] "BGA, 4-Leads, Pitch 0.5mm"
  round 0.25 smd mask+0.04: A1(-0.25,0.25) A2(0.25,0.25) B1(-0.25,-0.25) B2(0.25,-0.25)
  silkscreen extent -0.65,0.53 -0.55,0.62, body extent -0.5,-0.5 0.5,0.5, height 0.62
WL-SMCW_RED_0805 [mm] "SMD, 2-Leads, Body 1.6x0.8mm"
  rect 1.1x1.2 smd: 1(-1.05,0) 2(1.05,0)
  silkscreen extent -2.4,-1.1 1.5,1.1, body extent -1,-0.62 1,0.63, height 0.7

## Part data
C1 C10 C15: "CAP, CERM, 0.1 µF, 10 V, +/- 10%, X5R, 0402"
C2 C7: "CAP, AL, 2.7 µF, 500 V, +/- 20%, SMD"
C3 C8 C22 C23: "CAP, CERM, 100 pF, 50 V, +/- 5%, C0G/NP0, 0805"
C4: "CAP, CERM, 0.068 µF, 10 V, +/- 10%, X5R, 0402"
C5: "CAP, CERM, 1 µF, 10 V, +/- 10%, X5R, 0402"
C6: "CAP, CERM, 3.3 µF, 10 V, +/- 10%, X5R, 0603"
C9: "CAP, AL, 68 µF, 10 V, +/- 20%, 0.44 ohm, SMD"
C11 C14: "CAP, TA, 10 µF, 10 V, +/- 20%, 3 ohm, SMD"
C12 C13: "CAP, CERM, 1 µF, 10 V, +/- 10%, X7R, 0805"
C16 C17 C20 C27 C30: "CAP, CERM, 22 pF, 50 V, +/- 5%, C0G/NP0, 0805"
C18 C19 C42: "CAP, CERM, 10 pF, 100 V, +/- 5%, C0G/NP0, 0805"
C21 C25 C26 C32 C39 C40 C45: "CAP, CERM, 0.1 µF, 25 V, +/- 5%, X7R, 0603"
C24 C31 C37 C38 C44: "CAP, CERM, 1 µF, 16 V, +/- 10%, X7R, 0603"
C28 C29: "CAP, CERM, 220 pF, 50 V, +/- 5%, C0G/NP0, 0805"
C33 C34 C35 C36 C43: "CAP, CERM, 1000 pF, 25 V, +/- 10%, X7R, 0805"
C41: "CAP, CERM, 1300 pF, 50 V, +/- 5%, X7R, 0603"
D1: "Diode, P-N, 1000 V, 1 A, TH"
D2: "Diode, Ultrafast, 800 V, 1 A, 1408 Diode"
D3: "Diode, Zener, 3.6 V, 550 mW, SMB"
D4: "Diode, TVS, Bi, 400 V, 648 Vc, DO-214AB (no polarity)"
D5: "LED, Green, SMD"
D6: "Diode, Fast Rectifier, 600 V, 3 A, SMC"
D8: "LED, Red, SMD"
FID1 FID2 FID3: "Fiducial mark.  There is nothing to buy or mount."
H1 H2 H3 H4: "Machine Screw, Round, #4-40 x 1/4, Nylon, Philips panhead"
HV: library part IEC_HighVoltage, "IEC 61010-1 High Voltage Warning"
J2: "Header, 100mil, 4x1, TH"
J3 J4 J5 J6: "Header, 100mil, 2x1, Tin, TH"
J7: "TERM BLOCK 3POS 5.08MM, TH"
L1: "Inductor, Drum Core, Ferrite, 470 µH, 0.11 A, 14.3 ohm, SMD"
L2: "Inductor, Shielded, Ferrite, 1.2 mH, 0.84 A, 1.21 ohm, SMD"
L3: "Ferrite Bead, 330 ohm @ 100 MHz, 1.5 A, 0603"
LBL1: library part THT-14-423-10, "Thermal Transfer Printable Labels, 0.650\" W x 0.200\" H - 10,000 per roll"
Logo1: library part TI_Logo, "Texas Instrument Corporate Signature"
Logo2: library part Pb-Free
Logo3: library part FCC_disclaimer, "FCC_disclaimer"
Q1: "MOSFET, N-CH, 12 V, 1.6 A, 1x0.62x1mm"
R1: "RES, 39.7 k, 0.1%, 0.125 W, 0805"
R2: "RES, 10.2 k, 1%, 0.063 W, 0402"
R3 R5: "RES, 300, 5%, 0.1 W, 0603"
R4: "RES, 4.99 k, 1%, 0.063 W, 0402"
R6 R38: "RES, 100 k, 1%, 0.1 W, 0603"
R7 R10 R44 R46 R49: "RES, 47 k, 5%, 0.1 W, 0603"
R8 R9 R11 R39 R40: "RES, 0, 5%, 0.1 W, 0603"
R12 R13 R15 R16: "RES, 51 k, 5%, 0.125 W, 0805"
R14 R17 R22 R23 R30: "RES, 100 k, 1%, 0.125 W, 0805"
R18 R19 R20 R21: "RES, 10.0 k, 1%, 0.125 W, 0805"
R24 R25 R28 R29: "RES, 20.0 k, 1%, 0.125 W, 0805"
R26 R27: "RES, 180 k, 5%, 0.125 W, 0805"
R31 R35: "RES, 120 k, 5%, 0.125 W, 0805"
R32: "TRIMMER, 200k ohm, 0.15W, SMD"
R33: "RES, 3.40 k, 1%, 0.1 W, 0603"
R34: "RES, 3.83 M, 1%, 0.125 W, 0805"
R36: "RES, 200 k, 5%, 0.125 W, 0805"
R37: "RES, 29.4 k, 1%, 0.1 W, 0603"
R41: "RES, 402 k, 1%, 0.125 W, 0805"
R42: "RES, 0, 5%, 0.125 W, 0805"
R43: "RES, 1.0 k, 5%, 0.125 W, 0805"
R45: "RES, 300 k, 1%, 0.75 W, AEC-Q200 Grade 0, 2010"
R47: "RES, 10.0, 1%, 0.1 W, 0603"
R48: "RES, 1.10 k, 1%, 0.125 W, 0805"
RF1: "RES, 10, 5%, 3 W, TH, 2-Leads, Axial, Dia 5.5mm, Pin Spacing 23.8mm"
S1: "Switch, Tactile, SPST-NO, 0.02A, 15V, TH"
TP3 TP10 TP11 TP12 TP13 TP14 TP15 TP17: library part TP_SM_1MM, "1mm Test Point, SMT"
TP4 TP5 TP6 TP7 TP8 TP9: library part 0253-0-15-15-30-27-10-0, "Pin Receptacle, Dia 0.015-0.025\", Length 0.173\", Gold, TH"
U1: "700-V Lowest Quiescent Current Off-Line Switcher, D0007A"
U2: "ULTRA LOW-NOISE, 250-mA LINEAR REGULATOR FOR RF AND ANALOG CIRCUITS REQUIRES NO BYPASS CAPACITOR, DBV0005A"
U3: "Mixed-Signal Microcontroller, RGZ0048A"
U4: "Voltage Monitor With Watchdog Timer, DBV0005A (SOT-5)"
U5: "10-MHz, Rail-to-Rail Input/Output, Low-Voltage, 1.8-V CMOS Operational Amplifier, DBV0005A"
U6: "SINGLE-POLE DOUBLE-THROW ANALOG SWITCH, DRY0006A"
U7: "Ultra Low Power, Rail-to-Rail Out, Negative Rail In, VFB Amplifier, 2.5 to 5.5 V, -40 to 125 degC, 6-pin SOT23 (DBV6), Green (RoHS & no Sb/Br)"
U8: "Very Low Power, Rail to Rail Out, Negative Rail In, VFB Operational Amplifier, 2.5 to 5.5 V, -40 to 125 degC, 6-pin SOT23 (DBV6), Green (RoHS & no Sb/Br)"
U9: "40-ns, microPOWER, Push-Pull Output Comparators, DBV0005A"
U10: "Low Voltage Adjustable Precision Shunt Regulator, 39 ppm / degC, 15 mA, -40 to 85 degC, 3-pin SOT-23 (DBZ), Green (RoHS & no Sb/Br)"
U11: "Dual 1.4 MHz, Low Power General Purpose, 1.8V Op Amp, D0008A"
ZZ1: library part AssemblyNoteLabel
ZZ2 ZZ3 ZZ4: library part AssemblyNote

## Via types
v1: diameter 34, hole 16, Top Layer to Bottom Layer, 62 vias
v2: diameter 19.68, hole 7.87, Top Layer to Bottom Layer, 12 vias

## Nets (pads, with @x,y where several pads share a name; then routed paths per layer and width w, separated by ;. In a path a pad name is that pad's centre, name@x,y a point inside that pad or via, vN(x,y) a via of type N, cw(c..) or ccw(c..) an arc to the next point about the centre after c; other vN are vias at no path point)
+1.6V: R22.2 R23.2 R33.2 R37.2 R39.1 R49.1 U10.2 U11.6 | length 2681.4
  Top Layer w15: R49.1@250,962.8 250,1050 314.22,1050 316.59,1052.37 343.41,1052.37 362.37,1033.41 362.37,1017.63 410,970 470,970 520,920 520,620 560,580 ; U11.6@255,572.72 255,506.02 278.39,482.63 462.63,482.63 560,580 ; U10.2@760,669.16 730.84,669.16 703.44,696.56 R33.2@658.74,696.56 658.74,608.74 630,580 560,580
  Top Layer w30: U10.2@760,669.16 760,661.13 783.46,637.66 899.8,637.66 918.74,656.6 R37.2@918.74,856.56 R23.2@920,983.63 R22.2@920,1103.63 952.66,1103.63 v1(995.59,1146.56) ; v1(1125.59,1426.56) R39.1@1175.59,1472.11 ; 1148.32,1446.58 1148.32,1447.8
  Bottom Layer w30: v1(995.59,1146.56) 1065.59,1146.56 1125.59,1206.56 1125.59,1274.47 1127.23,1276.11 1127.23,1309.14 1125.59,1310.79 v1(1125.59,1426.56)
+3.3V: C6.1 C10.1 C11.1 C12.1 C21.1 C24.1 C25.1 C26.2 C31.1 C32.1 C37.1 C38.1 C39.1 C40.1 C44.1 C45.1 D3.1 J2.4 L3.2 R3.2 R5.1 R7.2 R30.2 R33.1 U2.5 U3.48 U4.5 U5.5 U6.5 U7.5 U7.6 U8.5 U8.6 U9.5 U11.8 | length 3584.1
  Top Layer w8: U6.5@575.59,1368.37 575.59,1386.56 585.59,1396.56
  Top Layer w10: 585.59,1396.56 605.59,1396.56 617.09,1408.06 C26.2@617.09,1436.56 v1(675.59,1436.56) ; C10.1@2559.67,1454.26 2559.67,1413.47 U3.48@2605.02,1368.12
  Top Layer w15: v1(985.59,1206.56) U7.5@985.59,1262.43 ; U8.6@1515.59,471.29 1515.59,440.95 v1(1557.95,440.95) ; 2142.97,686.9 U9.5@2142.97,746.23
  Top Layer w20: v1@148.5,568.5 148.5,605.87 190,647.36 190,711.73 163.23,738.5 150.24,738.5 ; v1(590,620) 590,647.86 595.75,653.61 R33.1@595.75,696.56 ; U7.5@985.59,1262.43 U7.6@1022.99,1262.43 1049.72,1262.43 1080.02,1232.13 C31.1@1141.2,1232.13 C32.1@1231.2,1232.13 ; U8.5@1475.59,473.88 U8.6@1512.99,473.88 ; U8.6@1515.59,471.29 U8.6@1512.99,473.88 ; C39.1@1760,495.07 C37.1@1670,495.07 1648.82,473.88 U8.6@1512.99,473.88 ; C24.1@1911.5,1626.56 1914,1599.3 1949.72,1565.06 U5.5@1949.72,1531.34 1985.2,1531.34 v1(1989.98,1526.56) ; v1(2111.18,656.56) 2121.18,656.56 2123.8,653.94 C38.1@2175.93,653.94 ; 2142.97,686.9 C38.1@2175.93,653.94 ; C40.1@2175.93,573.94 C38.1@2175.93,653.94 ; R30.2@2216.79,1013.63 v1(2216.79,1082.17) ; L3.2@2511.79,1792.36 2492.11,1772.67 2492.11,1630.05 2513.29,1608.86 C12.1@2513.29,1562.36 2498.65,1547.72 v1(2498.65,1454.26) C10.1@2559.67,1454.26 ; R7.2@2744.09,936.56 2744.09,985.07 2745.59,986.56 v1(2745.59,996.56) ; U2.5@2979.72,2503.96 3049.68,2503.96 C6.1@3055.59,2498.06 ; D3.1@2992.28,2210.73 D3.1@2992.28,2246.56 ; C21.1@3055.59,1198.06 3154.09,1198.06 3265.59,1086.56 3325.59,1086.56 3349.72,1062.43 U4.5@3349.72,1013.65 3392.99,1013.65 v1(3395.59,1016.25) ; R5.1@3325.59,1538.06 3384.09,1538.06 3387.6,1541.56 v1(3390.59,1541.56)
  Top Layer w25: C44.1@100,568.5 v1@148.5,568.5 ; C45.1@100,738.5 150.24,738.5 ; U11.8@355,572.72 v1(393.27,575) ; v1@385.55,572.72 v1@388.27,570
  Top Layer w30: C24.1@1911.5,1626.56 C25.1@1911.5,1706.56 ; U2.5@2979.72,2503.96 2979.72,2550.7 v1(2980.59,2551.56) ; D3.1@2992.28,2210.73 3046.77,2156.25 R3.2@3046.77,2086.56 ; D3.1@2992.28,2246.56 3115.59,2369.87 3115.59,2479.55 3097.09,2498.06 C6.1@3055.59,2498.06
  other v1: 155,570
+5V: C5.1 C9.1 D2.2 L2.2 R4.2 U2.1 U2.3 | length 2382.9
  Top Layer w20: R4.2@1855.59,2260.18 1855.59,2416.56 1915.59,2476.56 2115.59,2476.56 2131.69,2492.66 D2.2@2131.69,2546.56
  Top Layer w25: C9.1@2375.59,2082.86 2571.89,2082.86 2662.6,2173.57 L2.2@2662.6,2436.56 ; U2.3@2871.46,2429.16 2871.46,2424.24 2853.78,2406.56 2692.6,2406.56 L2.2@2662.6,2436.56 ; U2.1@2871.46,2503.96 2865.24,2510.18 C5.1@2795.59,2510.18 2736.22,2510.18 L2.2@2662.6,2436.56
  Top Layer w30: D2.2@2131.69,2546.56 2131.69,2642.66 2609.49,2642.66 2662.6,2589.55 L2.2@2662.6,2436.56
ADC_HF: C42.1 R43.1 U3.3 | length 989.3
  Top Layer w8: 2537.88,1303.16 U3.3@2579.43,1303.16
  Top Layer w10: 2412.18,1303.16 2501.37,1303.16 2502.75,1301.78 2536.5,1301.78
  Top Layer w30: R43.1@1695.59,1046.56 C42.1@1805.59,1046.56 1865.59,1046.56 2055.59,1236.56 2345.59,1236.56 2412.18,1303.16
ADC_LF: C18.1 R41.2 TP4.1 U3.1 | length 586.7
  Top Layer w8: 2519.63,1342.53 U3.1@2579.43,1342.53
  Top Layer w20: TP4.1@2280,1396.56 2465.59,1396.56 2519.63,1342.53
  Top Layer w30: C18.1@2140,1466.56 R41.2@2139.98,1556.56 R41.2@2139.98,1576.56 ; C18.1@2150,1456.56 2220,1456.56 TP4.1@2280,1396.56
ADC_VIN: R47.2 TP12.1 U3.11 U11.5 | length 3470.4
  Top Layer w8: 2534.7,1145.68 U3.11@2579.43,1145.68
  Top Layer w10: TP12.1@2485.59,1096.56 2534.7,1145.68
  Top Layer w12: v1(210,500) 210,510 205,515 U11.5@205,572.72 205,598.91 208.98,602.89 208.98,618.98 228.5,638.5 R47.2@460,638.5 ; TP12.1@2485.59,1096.56 2510,1072.15 v1(2510,1070)
  Bottom Layer w12: v1(210,500) 280,430 548.65,430 588.65,390 2360,390 2480,510 2480,1000 2510,1030 v1(2510,1070)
